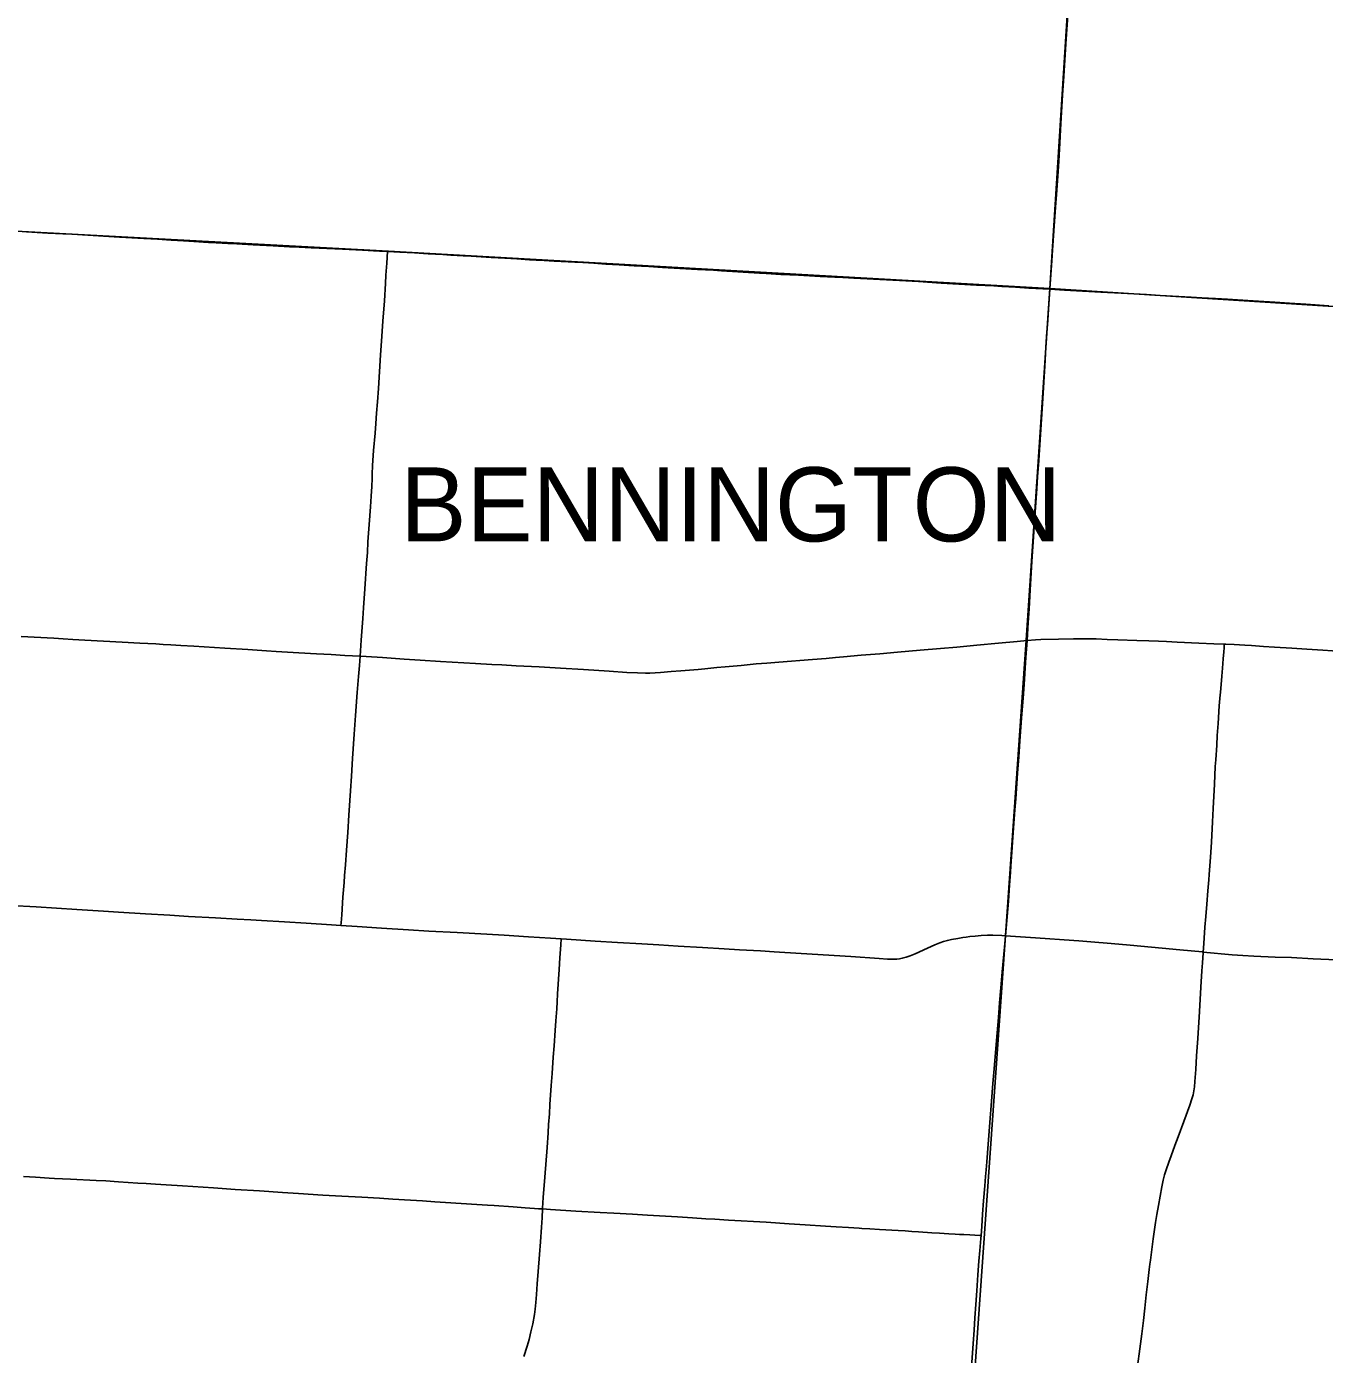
# Model space of a CAD drawing. Extents: x 9078 to 9739, y 4248 to 4966.
# Drawn here: x 9448.2 to 9527, y 4346.3 to 4427 of the extents above; entities that cross this region are included whole.
import ezdxf

# ---------------------------------------------------------------- set-up
doc = ezdxf.new("R2010")
doc.units = 0
for name, color, linetype in [('GM_X_County_Road', 7, 'Continuous'), ('GM_X_State_Route', 7, 'Continuous'), ('GM_X_Township', 7, 'Continuous'), ('GM_X_Township_Road', 7, 'Continuous'), ('GM_X_Township_Text', 7, 'Continuous')]:
    doc.layers.add(name, color=color, linetype=linetype)

msp = doc.modelspace()

# ---------------------------------------------------------------- linework, layer by layer
at = {"layer": 'GM_X_County_Road'}
for points in [[(9510.319, 4411.026), (9510.346, 4411.356), (9510.447, 4412.743), (9510.487, 4413.398), (9510.52, 4413.97), (9510.622, 4415.442), (9510.677, 4416.26), (9510.711, 4416.75), (9510.8, 4417.894), (9510.856, 4418.794), (9510.895, 4419.53), (9510.992, 4421.085), (9511.088, 4422.803), (9511.162, 4423.948), (9511.297, 4425.911), (9511.385, 4427.384), (9511.418, 4427.964)], [(9508.94, 4389.693), (9509.005, 4390.793), (9509.054, 4391.612), (9509.124, 4392.759), (9509.233, 4394.478), (9509.345, 4396.28), (9509.47, 4398.08), (9509.517, 4398.9), (9509.569, 4399.636), (9509.64, 4400.618), (9509.688, 4401.273), (9509.765, 4402.501), (9509.893, 4404.384), (9509.955, 4405.367), (9510.014, 4406.35), (9510.08, 4407.496), (9510.121, 4408.151), (9510.19, 4409.133), (9510.262, 4410.115), (9510.319, 4411.026)], [(9510.319, 4411.026), (9511.198, 4410.971), (9511.935, 4410.93), (9513.409, 4410.841), (9514.637, 4410.774), (9516.193, 4410.691), (9517.013, 4410.645), (9518.896, 4410.536), (9519.552, 4410.503), (9520.371, 4410.452), (9521.108, 4410.409), (9522.337, 4410.341), (9522.991, 4410.295), (9523.973, 4410.228), (9524.874, 4410.172), (9525.856, 4410.11), (9527.247, 4410.016)], [(9507.629, 4371.758), (9507.703, 4372.699), (9507.798, 4373.854), (9507.874, 4374.836), (9507.925, 4375.621), (9507.948, 4375.983), (9507.983, 4376.555), (9508.098, 4378.027), (9508.199, 4379.418), (9508.249, 4380.073), (9508.358, 4381.628), (9508.431, 4382.61), (9508.503, 4383.591), (9508.605, 4384.983), (9508.717, 4386.455), (9508.759, 4387.028), (9508.801, 4387.683), (9508.866, 4388.665), (9508.94, 4389.693)]]:
    msp.add_lwpolyline(points, dxfattribs=at)
at = {"layer": 'GM_X_State_Route'}
msp.add_lwpolyline([(9447.232, 4373.61), (9448.788, 4373.519), (9451.243, 4373.35), (9452.881, 4373.25), (9453.782, 4373.193), (9455.42, 4373.1), (9456.894, 4373.011), (9458.04, 4372.942), (9459.679, 4372.851), (9460.989, 4372.779), (9461.808, 4372.727), (9462.463, 4372.686), (9463.855, 4372.602), (9465.165, 4372.522), (9466.721, 4372.427), (9467.285, 4372.392), (9468.277, 4372.33), (9469.75, 4372.232), (9471.388, 4372.126), (9472.616, 4372.047), (9474.335, 4371.952), (9476.137, 4371.853), (9477.202, 4371.793), (9478.676, 4371.699), (9479.997, 4371.621), (9480.648, 4371.578), (9480.969, 4371.557), (9482.725, 4371.445), (9484.081, 4371.363), (9485.555, 4371.279), (9486.589, 4371.213), (9487.765, 4371.141), (9489.24, 4371.052), (9490.55, 4370.977), (9491.476, 4370.919), (9492.761, 4370.84), (9493.579, 4370.783), (9495.217, 4370.687), (9498.246, 4370.503), (9499.964, 4370.373), (9500.456, 4370.346), (9500.785, 4370.342), (9501.033, 4370.35), (9501.198, 4370.367), (9501.361, 4370.395), (9501.601, 4370.457), (9501.835, 4370.538), (9502.139, 4370.666), (9502.881, 4371.017), (9503.329, 4371.218), (9503.633, 4371.339), (9503.865, 4371.417), (9504.101, 4371.481), (9504.34, 4371.531), (9504.741, 4371.602), (9505.036, 4371.649), (9505.232, 4371.68), (9505.459, 4371.711), (9505.774, 4371.747), (9506.152, 4371.778), (9506.535, 4371.791), (9506.862, 4371.792), (9507.397, 4371.773), (9507.629, 4371.758), (9509.137, 4371.664), (9510.036, 4371.602), (9511.18, 4371.524), (9512.08, 4371.454), (9512.815, 4371.392), (9514.04, 4371.284), (9515.184, 4371.186), (9517.145, 4371.012), (9518.205, 4370.905), (9519.588, 4370.779), (9519.628, 4370.776), (9521.386, 4370.611), (9522.04, 4370.565), (9522.694, 4370.528), (9524.003, 4370.472), (9524.987, 4370.434), (9526.297, 4370.368), (9528.673, 4370.27)], dxfattribs=at)
at = {"layer": 'GM_X_Township'}
for points in [[(9646.564, 4403.186), (9632.593, 4403.992), (9619.889, 4404.725), (9619.129, 4404.769), (9590.635, 4406.413), (9575.396, 4407.069), (9562.089, 4407.805), (9537.409, 4409.337), (9510.323, 4411.058), (9511.38, 4427.966), (9511.83, 4435.772), (9511.888, 4436.239), (9513.121, 4453.992), (9514.674, 4478.861), (9516.207, 4506.231), (9517.263, 4528.671), (9517.499, 4532.736), (9518.307, 4546.633)], [(9443.397, 4414.764), (9470.181, 4413.322), (9510.323, 4411.058), (9508.882, 4389.718), (9507.617, 4371.786), (9503.704, 4316.052), (9503.082, 4307.19), (9501.141, 4279.539)]]:
    msp.add_lwpolyline(points, dxfattribs=at)
at = {"layer": 'GM_X_Township_Road'}
for points in [[(9448.19, 4414.497), (9449.498, 4414.431), (9450.403, 4414.381), (9450.976, 4414.353), (9451.922, 4414.298), (9453.189, 4414.223), (9453.845, 4414.189), (9454.583, 4414.145), (9455.321, 4414.109), (9456.141, 4414.064), (9456.971, 4413.999), (9457.72, 4413.954), (9458.347, 4413.916), (9459.252, 4413.86), (9459.706, 4413.833), (9460.427, 4413.799), (9460.974, 4413.77), (9461.958, 4413.721), (9463.179, 4413.655), (9464.166, 4413.6), (9464.754, 4413.572), (9465.484, 4413.533), (9467.371, 4413.444), (9468.602, 4413.381), (9469.258, 4413.346), (9469.631, 4413.323), (9470.119, 4413.301)], [(9468.444, 4388.733), (9468.51, 4389.716), (9468.608, 4391.023), (9468.652, 4391.677), (9468.726, 4392.821), (9468.838, 4394.374), (9468.887, 4395.028), (9468.926, 4395.682), (9469.001, 4396.744), (9469.079, 4397.807), (9469.123, 4398.461), (9469.154, 4399.036), (9469.181, 4399.527), (9469.188, 4399.796), (9469.209, 4400.322), (9469.264, 4401.227), (9469.354, 4402.278), (9469.401, 4402.874), (9469.443, 4403.501), (9469.5, 4404.18), (9469.558, 4404.997), (9469.688, 4407.041), (9469.74, 4407.859), (9469.828, 4409.085), (9469.922, 4410.311), (9469.987, 4411.373), (9470.017, 4411.864), (9470.064, 4412.599), (9470.119, 4413.301)], [(9470.119, 4413.301), (9470.852, 4413.266), (9471.752, 4413.22), (9472.57, 4413.177), (9473.47, 4413.124), (9473.96, 4413.092), (9474.695, 4413.049), (9475.186, 4413.022), (9476.414, 4412.955), (9477.232, 4412.908), (9477.967, 4412.861), (9478.735, 4412.814), (9479.134, 4412.792), (9479.622, 4412.764), (9480.227, 4412.731), (9481.074, 4412.678), (9481.483, 4412.66), (9481.974, 4412.634), (9482.629, 4412.596), (9483.365, 4412.549), (9484.182, 4412.494), (9484.754, 4412.457), (9485.081, 4412.442), (9485.98, 4412.396), (9486.798, 4412.348), (9487.862, 4412.286), (9488.925, 4412.222), (9489.415, 4412.196), (9489.905, 4412.17), (9490.395, 4412.138), (9491.704, 4412.06), (9492.685, 4412.001), (9493.094, 4411.977), (9493.993, 4411.922), (9495.057, 4411.863), (9496.366, 4411.793), (9497.266, 4411.752), (9497.757, 4411.724), (9498.411, 4411.688), (9499.229, 4411.644), (9500, 4411.601), (9501.192, 4411.541), (9502.338, 4411.483), (9503.728, 4411.397), (9505.855, 4411.267), (9506.918, 4411.217), (9507.409, 4411.193), (9508.227, 4411.138), (9509.045, 4411.09), (9510.319, 4411.026)], [(9447.868, 4389.942), (9449.862, 4389.824), (9450.414, 4389.789), (9451.012, 4389.754), (9451.738, 4389.708), (9452.864, 4389.66), (9454.01, 4389.599), (9455.075, 4389.539), (9456.057, 4389.482), (9456.499, 4389.453), (9456.969, 4389.43), (9457.568, 4389.389), (9458.349, 4389.35), (9460.232, 4389.232), (9461.624, 4389.139), (9462.77, 4389.068), (9463.343, 4389.033), (9464.735, 4388.95), (9465.799, 4388.885), (9466.7, 4388.831), (9467.519, 4388.788), (9468.444, 4388.733)], [(9468.444, 4388.733), (9468.821, 4388.711), (9469.811, 4388.654), (9471.121, 4388.565), (9472.103, 4388.501), (9473.331, 4388.423), (9475.461, 4388.292), (9476.443, 4388.239), (9477.048, 4388.207), (9477.917, 4388.158), (9479.31, 4388.084), (9480.621, 4388.008), (9482.013, 4387.924), (9483.569, 4387.827), (9484.633, 4387.758), (9485.288, 4387.722), (9485.78, 4387.708), (9486.026, 4387.711), (9486.68, 4387.755), (9487.335, 4387.805), (9487.907, 4387.846), (9488.969, 4387.939), (9489.377, 4387.98), (9490.112, 4388.047), (9490.602, 4388.09), (9491.582, 4388.181), (9492.481, 4388.265), (9493.135, 4388.318), (9493.871, 4388.375), (9495.915, 4388.542), (9496.733, 4388.606), (9497.305, 4388.655), (9497.795, 4388.702), (9498.858, 4388.791), (9500.002, 4388.884), (9501.065, 4388.974), (9502.455, 4389.097), (9503.68, 4389.206), (9504.661, 4389.292), (9505.887, 4389.403), (9507.194, 4389.523), (9508.338, 4389.629), (9508.94, 4389.693)], [(9508.94, 4389.693), (9509.449, 4389.736), (9509.775, 4389.748), (9510.842, 4389.773), (9511.743, 4389.798), (9512.318, 4389.8), (9513.138, 4389.783), (9513.793, 4389.758), (9514.449, 4389.729), (9515.597, 4389.688), (9516.334, 4389.661), (9516.907, 4389.641), (9517.399, 4389.621), (9518.054, 4389.589), (9519.366, 4389.536), (9520.267, 4389.497), (9520.906, 4389.467)], [(9520.659, 4386.389), (9520.672, 4386.541), (9520.763, 4387.522), (9520.801, 4388.014), (9520.846, 4388.586), (9520.879, 4388.995), (9520.893, 4389.242), (9520.906, 4389.467)], [(9520.906, 4389.467), (9521.005, 4389.462), (9521.496, 4389.441), (9522.15, 4389.407), (9522.559, 4389.384), (9523.296, 4389.336), (9523.951, 4389.295), (9525.015, 4389.222), (9525.915, 4389.161), (9526.897, 4389.098), (9527.47, 4389.063), (9529.27, 4388.937), (9531.071, 4388.814), (9532.871, 4388.691), (9533.607, 4388.64), (9534.59, 4388.583), (9534.673, 4388.579)], [(9467.285, 4372.392), (9467.297, 4372.553), (9467.335, 4373.043), (9467.409, 4374.106), (9467.484, 4375.004), (9467.511, 4375.413), (9467.556, 4376.067), (9467.622, 4376.965), (9467.696, 4378.028), (9467.769, 4379.091), (9467.866, 4380.563), (9467.929, 4381.461), (9467.995, 4382.524), (9468.095, 4383.996), (9468.178, 4385.14), (9468.276, 4386.53), (9468.359, 4387.509), (9468.407, 4388.163), (9468.444, 4388.733)], [(9519.628, 4370.776), (9519.668, 4371.302), (9519.735, 4372.285), (9519.785, 4372.94), (9519.847, 4373.677), (9519.909, 4374.496), (9519.965, 4375.151), (9519.992, 4375.477), (9520.073, 4376.54), (9520.131, 4377.441), (9520.188, 4378.671), (9520.23, 4379.491), (9520.31, 4380.967), (9520.358, 4382.034), (9520.387, 4382.443), (9520.446, 4383.346), (9520.482, 4383.919), (9520.53, 4384.657), (9520.604, 4385.723), (9520.659, 4386.389)], [(9479.519, 4355.176), (9479.521, 4355.218), (9479.569, 4355.873), (9479.656, 4357.101), (9479.797, 4358.902), (9479.861, 4359.802), (9479.892, 4360.294), (9479.935, 4360.949), (9479.975, 4361.522), (9480.055, 4362.669), (9480.106, 4363.406), (9480.169, 4364.388), (9480.224, 4365.089), (9480.29, 4366.006), (9480.328, 4366.599), (9480.381, 4367.335), (9480.406, 4367.745), (9480.435, 4368.237), (9480.53, 4369.709), (9480.571, 4370.423), (9480.623, 4371.209), (9480.648, 4371.578)], [(9506.139, 4353.557), (9506.179, 4354.119), (9506.236, 4354.86), (9506.297, 4355.678), (9506.365, 4356.578), (9506.412, 4357.149), (9506.446, 4357.557), (9506.485, 4358.047), (9506.577, 4359.11), (9506.675, 4360.419), (9506.779, 4361.727), (9506.861, 4362.79), (9506.937, 4363.69), (9507.073, 4365.407), (9507.199, 4366.796), (9507.269, 4367.696), (9507.336, 4368.596), (9507.423, 4369.576), (9507.524, 4370.638), (9507.585, 4371.291), (9507.629, 4371.758)], [(9515.609, 4345.485), (9515.735, 4346.378), (9515.896, 4347.597), (9515.998, 4348.411), (9516.083, 4349.144), (9516.173, 4349.958), (9516.264, 4350.772), (9516.349, 4351.504), (9516.394, 4351.829), (9516.427, 4352.072), (9516.525, 4352.883), (9516.589, 4353.37), (9516.729, 4354.344), (9516.806, 4354.83), (9516.908, 4355.393), (9517.016, 4355.956), (9517.117, 4356.521), (9517.202, 4356.922), (9517.286, 4357.239), (9517.383, 4357.552), (9517.541, 4358.017), (9517.673, 4358.405), (9517.895, 4359.022), (9518.102, 4359.557), (9518.442, 4360.48), (9518.812, 4361.48), (9518.942, 4361.868), (9519.008, 4362.105), (9519.058, 4362.346), (9519.095, 4362.589), (9519.127, 4362.915), (9519.179, 4363.651), (9519.226, 4364.47), (9519.296, 4365.534), (9519.396, 4367.17), (9519.485, 4368.643), (9519.546, 4369.625), (9519.58, 4370.115), (9519.624, 4370.726), (9519.628, 4370.776)], [(9448.011, 4357.154), (9448.747, 4357.099), (9449.565, 4357.047), (9449.893, 4357.027), (9450.876, 4356.978), (9452.434, 4356.912), (9453.007, 4356.876), (9453.784, 4356.823), (9454.367, 4356.782), (9454.95, 4356.746), (9455.456, 4356.715), (9456.033, 4356.684), (9456.68, 4356.643), (9457.671, 4356.584), (9459.553, 4356.452), (9460.863, 4356.366), (9462.337, 4356.268), (9463.729, 4356.182), (9464.712, 4356.118), (9466.185, 4356.023), (9467.339, 4355.953), (9468.56, 4355.882), (9469.625, 4355.823), (9470.444, 4355.775), (9471.508, 4355.71), (9472.245, 4355.663), (9472.981, 4355.613), (9473.637, 4355.572), (9474.587, 4355.504), (9475.531, 4355.447), (9476.174, 4355.404), (9476.584, 4355.38), (9477.735, 4355.303), (9478.466, 4355.25), (9479.037, 4355.211), (9479.283, 4355.193), (9479.475, 4355.179), (9479.519, 4355.176)], [(9478.391, 4346.22), (9478.588, 4346.846), (9478.701, 4347.24), (9478.82, 4347.717), (9478.924, 4348.198), (9479.03, 4348.762), (9479.077, 4349.085), (9479.118, 4349.491), (9479.15, 4349.979), (9479.196, 4350.633), (9479.254, 4351.37), (9479.335, 4352.409), (9479.39, 4353.171), (9479.453, 4354.071), (9479.491, 4354.644), (9479.519, 4355.176)], [(9479.519, 4355.176), (9479.998, 4355.146), (9481.553, 4355.05), (9483.027, 4354.957), (9483.846, 4354.912), (9484.992, 4354.851), (9485.893, 4354.801), (9486.629, 4354.751), (9487.724, 4354.69), (9488.632, 4354.628), (9489.432, 4354.582), (9489.986, 4354.549), (9490.805, 4354.5), (9493.097, 4354.364), (9494.489, 4354.272), (9495.471, 4354.212), (9496.699, 4354.136), (9497.354, 4354.094), (9498.09, 4354.048), (9498.743, 4354.008), (9498.906, 4353.993), (9499.397, 4353.968), (9499.97, 4353.934), (9501.116, 4353.868), (9501.525, 4353.842), (9501.934, 4353.814), (9502.343, 4353.788), (9503.158, 4353.732), (9503.623, 4353.706), (9504.19, 4353.669), (9504.567, 4353.649), (9504.831, 4353.633), (9505.089, 4353.623), (9505.46, 4353.597), (9506.069, 4353.561), (9506.139, 4353.557)], [(9505.355, 4342.389), (9505.366, 4342.587), (9505.405, 4343.242), (9505.465, 4344.142), (9505.581, 4345.861), (9505.657, 4347.007), (9505.718, 4347.825), (9505.768, 4348.562), (9505.82, 4349.381), (9505.877, 4350.199), (9505.942, 4351.182), (9506.008, 4351.999), (9506.064, 4352.653), (9506.127, 4353.389), (9506.139, 4353.557)]]:
    msp.add_lwpolyline(points, dxfattribs=at)

# ---------------------------------------------------------------- texts
at = {"layer": 'GM_X_Township_Text'}
msp.add_text('BENNINGTON', height=4.5, rotation=0.00001, dxfattribs=at).set_placement((9470.892, 4395.707))

doc.saveas('drawing.dxf')
